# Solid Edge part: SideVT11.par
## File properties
Author: harmonj5
Template: ansi part.par
Last saved by: harmonj5
Revision: 8
Application: Solid Edge
Accuracy: 0.990
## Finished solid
Body 1: solid body, 53 faces, 147 edges, 98 vertices, 2 separate solids.
  Faces by surface: plane 39, cylinder 7, swept 7
  Edges by curve: line 119, circle 14, spline 14
Bounding box of the edges (mm; curved faces can reach further): 187.481 x 22.561 x 3.175, from (-216.0372, 111.6518, -3.175) to (-28.5558, 134.2126, 0).
Cylindrical faces by radius (mm): R1.5875 x1, R3.175 x2, R136.3416 x1, R397.9207 x1, R1027.8943 x1, R1088.2106 x1
Planar faces by outward normal: +x 10, +y 5, +z 2, -x 4, -y 5, -z 2, oblique 11
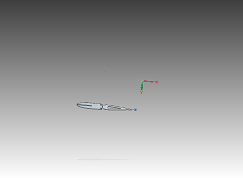
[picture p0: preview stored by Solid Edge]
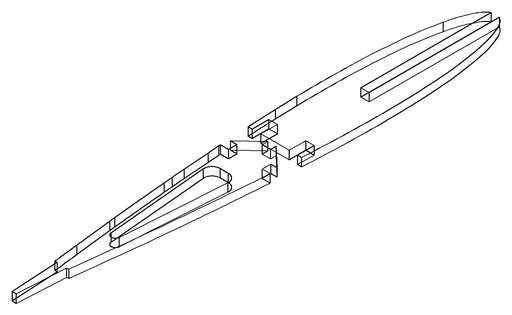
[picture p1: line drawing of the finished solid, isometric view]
